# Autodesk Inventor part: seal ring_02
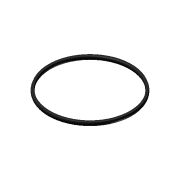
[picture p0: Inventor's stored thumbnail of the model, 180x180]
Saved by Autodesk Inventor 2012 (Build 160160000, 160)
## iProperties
Created: 2002-03
Part Number: seal ring_02
Document SubType Name: Modeling
Designer: Lieven Grauls
Stock Number: seal ring_02
Project: Valve Techcamp 2008
Density: 1 g/cm^3
Mass: 0.260004 g
Surface Area: 21.7473 cm^2
Volume: 0.260004 cm^3
Material: Default
Company: Autodesk
Control State: 0
Master: False
Checked Out: False
Shininess: 64.0
Length Units: 11272
Angle Units: 11279
Time Units: 11290
Mass Units: 11286
Length Display Precision: 3
Angle Display Precision: 2
Density: 0.0
Volumn: 0.0
Area: 0.0
PropertySet Name: Model Information
Author: Lieven Grauls
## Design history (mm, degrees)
sketch "Sketch1"
  geometry: L1 (0, 6.115)-(0, -5.303) reference; L2 (-5.158, 0)-(30.949, 0) reference; L3 (23.94, 2.134)-(25.718, 2.134); L4 (25.718, 2.134)-(25.718, 0); L5 (25.718, 0)-(23.94, 0); L6 (23.94, 0)-(23.94, 2.134); L7 (24.829, 2.134)-(24.829, 0); L8 (24.375, 2.134)-(24.375, 1.934); L9 (24.398, 0.175)-(24.398, 0); L10 (25.282, 2.134)-(25.282, 1.934); L11 (25.259, 0.175)-(25.259, 0); L12 (24.375, 1.539)-(25.282, 1.539); L13 (23.94, 4.484)-(23.94, -3.672); L14 (24.375, 2.134)-(25.282, 2.134); L15 (24.22, 0)-(24.398, 0); L16 (25.259, 0)-(25.437, 0); C1 r 0.643 at (24.829, 0.897); C2 r 0.469 at (24.829, 0.897); A1 r 1.506 centre (25.446, 0.875) between (24.375, 1.934) and (24.22, 0); A2 r 1.26 centre (25.446, 0.875) between (24.375, 1.539) and (24.398, 0.175); A3 r 1.506 centre (24.211, 0.875) between (25.437, 0) and (25.282, 1.934); A4 r 1.26 centre (24.211, 0.875) between (25.259, 0.175) and (25.282, 1.539); 2 further points
  constraints: 28 end point, 8 point on circle, 7 symmetric about line, 6 centre point, 5 point on line, 4 parallel, 4 perpendicular, 2 midpoint, 2 tangent, 1 coincident, 1 collinear, 1 horizontal, 1 horizontal alignment, 4 other
  dimensions: "d5" = 1.778 distance of L3.start L3.end; "d6" = 2.1336 distance of L3.end L4.end; "d10" = 47.879 diameter of L13 L1; "d12" = 2.1336 vertical distance of point (23.94, 2.134) point (0, 0)
revolve "Revolution1" sketch "Sketch1" stored, may be unused: angle "d3" = 90 deg
sketch "Sketch2"
  geometry: L1 (-5.08, 5.08)-(-5.08, 25.211); L2 (-5.08, 5.08)-(-25.211, 5.08); L3 (0, 39.044)-(0, -36.511) reference; L4 (36.511, 0)-(-39.044, 0) reference; A1 r 25.718 centre (0, 0) between (-5.08, 25.211) and (-25.211, 5.08) reference; A2 r 25.718 centre (0, 0) between (-5.08, 25.211) and (-25.211, 5.08); 1 further point
  constraints: 4 end point, 4 point on circle, 1 centre point, 1 coincident, 1 perpendicular, 1 vertical
  dimensions: "d13" = 5.08 distance between parallel lines of L2 L4; "d14" = 5.08 distance between parallel lines of L3 L1 (= d13)
extrude "Extrusion1" cut sketch "Sketch2" stored distance "d15" = 25.4; taper "d16" = 0 deg
node "Volumenkörper1"
node "Volumenkörpern"
node "Oberflächenkörpern"
